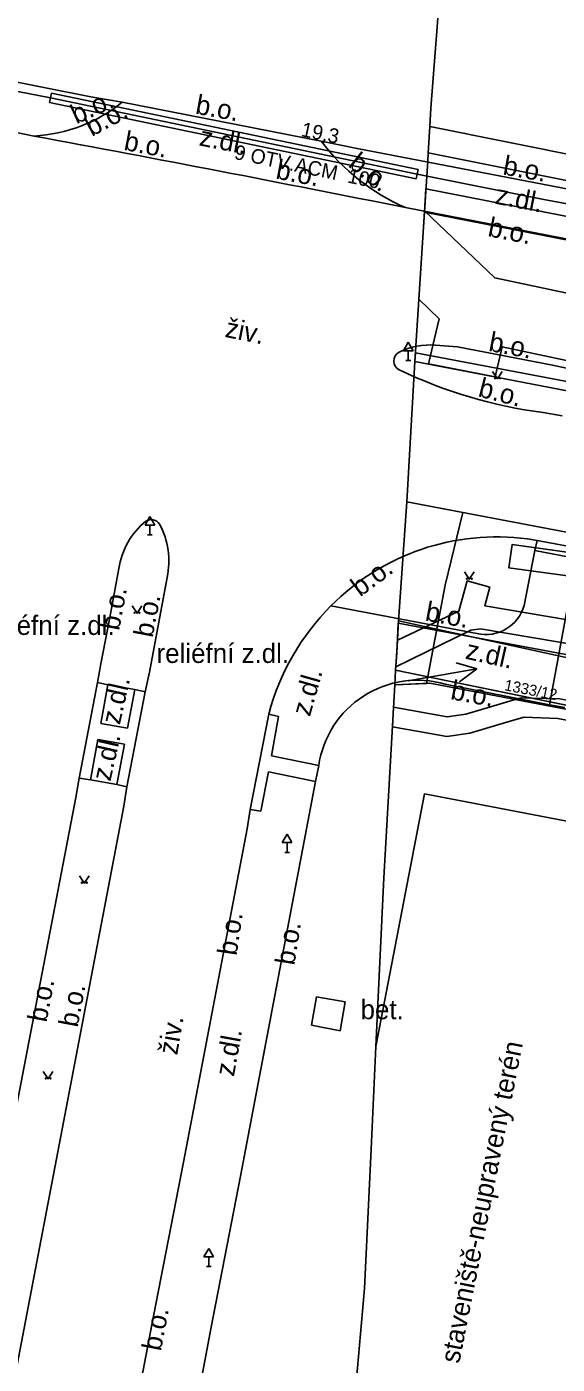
# Model space of a CAD drawing. Extents: x -601602 to -600882, y -1162594 to -1161950.
# Drawn here: x -601508 to -601480.7, y -1162340.4 to -1162271.4 of the extents above; entities that cross this region are included whole.
import ezdxf

# ---------------------------------------------------------------- set-up
doc = ezdxf.new("R2010")
doc.units = 0
for name, color, linetype in [('KN_Hranice parcel', 7, 'Continuous'), ('KN_Parcelní čísla', 7, 'Continuous'), ('KN_Pop  PČ popisy', 7, 'Continuous'), ('KN_Vnitřní kresba', 7, 'Continuous'), ('KN_Věcná břemena k části', 7, 'Continuous'), ('VRSTVA 1', 7, 'Continuous'), ('Vrstva 13', 7, 'Continuous'), ('Vrstva 14', 7, 'Continuous'), ('Vrstva 16', 7, 'Continuous'), ('VRSTVA 3', 7, 'Continuous'), ('VRSTVA 5', 7, 'Continuous'), ('Vrstva 6', 7, 'Continuous'), ('Vrstva 8', 7, 'Continuous')]:
    doc.layers.add(name, color=color, linetype=linetype)

# ---------------------------------------------------------------- blocks, each defined once
blk = doc.blocks.new('1029_83')
at = {"layer": 'KN_Pop  PČ popisy'}
for p, q in [((2.955, 0.521), (1.882, 0.84)), ((0, 0), (2.955, 0.521)), ((2.955, 0.521), (2.056, -0.146))]:
    blk.add_line(p, q, dxfattribs=at)

msp = doc.modelspace()

# ---------------------------------------------------------------- linework, layer by layer
at = {"layer": 'KN_Hranice parcel'}
for p, q in [((-601487.18, -1162275.61), (-601486.34, -1162264.83)), ((-601487.24, -1162276.56), (-601487.18, -1162275.61)), ((-601487.33, -1162277.91), (-601487.24, -1162276.56)), ((-601487.24, -1162276.56), (-601422.4, -1162289.56)), ((-601487.35, -1162278.35), (-601487.33, -1162277.91)), ((-601487.57, -1162281.75), (-601487.35, -1162278.35)), ((-601487.71, -1162283.88), (-601487.57, -1162281.75)), ((-601488.01, -1162288.67), (-601487.71, -1162283.88)), ((-601488.01, -1162288.67), (-601488.43, -1162295.92)), ((-601488.86, -1162302.06), (-601488.43, -1162295.92)), ((-601488.43, -1162295.92), (-601466.03, -1162300.16)), ((-601488.95, -1162303.71), (-601488.86, -1162302.06)), ((-601489.01, -1162304.59), (-601488.95, -1162303.71)), ((-601489.01, -1162304.59), (-601489.05, -1162305.35)), ((-601465.65, -1162309.39), (-601489.01, -1162304.59)), ((-601489.05, -1162305.35), (-601489.61, -1162315.31)), ((-601489.61, -1162315.31), (-601490.02, -1162324)), ((-601490.02, -1162324), (-601490.27, -1162329.3))]:
    msp.add_line(p, q, dxfattribs=at)
for points in [[(-601487.33, -1162277.91), (-601423.31, -1162290.7), (-601422.78, -1162290.75), (-601418.98, -1162290.19)], [(-601346.72, -1162315.75), (-601358.39, -1162313.5), (-601389.94, -1162307.57), (-601406.17, -1162304.44), (-601488.01, -1162288.67)], [(-601489.05, -1162305.35), (-601487.24, -1162305.27), (-601465.65, -1162309.39)], [(-601465.12, -1162315.27), (-601487.52, -1162310.98), (-601490.02, -1162324)], [(-601490.27, -1162329.3), (-601490.61, -1162336.49), (-601491.28, -1162344.08)]]:
    msp.add_lwpolyline(points, dxfattribs=at)
at = {"layer": 'KN_Pop  PČ popisy'}
msp.add_line((-601488.35, -1162305.15), (-601487.77, -1162305.05), dxfattribs=at)
at = {"layer": 'KN_Vnitřní kresba'}
msp.add_line((-601488.86, -1162302.06), (-601425, -1162316), dxfattribs=at)
at = {"layer": 'KN_Věcná břemena k části'}
for points in [[(-601342.91, -1162315.69), (-601475.53, -1162290.59), (-601474.19, -1162283.58), (-601472.3, -1162283.95), (-601472.05, -1162282.78), (-601487.44, -1162279.77), (-601487.52, -1162280.97), (-601475.37, -1162283.35), (-601476.71, -1162290.36), (-601487.98, -1162288.23), (-601488.01, -1162288.67), (-601406.17, -1162304.44)], [(-601470.29, -1162303.67), (-601484.41, -1162301.27), (-601484.15, -1162300.31), (-601485.31, -1162299.99), (-601485.74, -1162301.55), (-601488.91, -1162303.05), (-601489, -1162304.43), (-601485.13, -1162302.53), (-601484.63, -1162302.46), (-601471.08, -1162304.75)], [(-601429.98, -1162315.75), (-601480.53, -1162306.08), (-601481.97, -1162306.04), (-601482.51, -1162306.02), (-601482.83, -1162306.11), (-601465.65, -1162309.39), (-601426.59, -1162316.85)]]:
    msp.add_lwpolyline(points, dxfattribs=at)
for points in [[(-601319.34, -1162319.73), (-601318.72, -1162316.39), (-601326.64, -1162314.93), (-601327.32, -1162314.81), (-601389.66, -1162303.33), (-601388.27, -1162295.89), (-601391.51, -1162295.29), (-601392.9, -1162302.72), (-601436.53, -1162294.41), (-601483.89, -1162284.37), (-601487.52, -1162280.9), (-601487.57, -1162281.75), (-601487.71, -1162283.88), (-601487.81, -1162285.47), (-601486.76, -1162286.48), (-601487.31, -1162288.8), (-601483.87, -1162289.47), (-601483.5, -1162287.92), (-601437.21, -1162297.75), (-601391.91, -1162306.37), (-601327.93, -1162318.15), (-601327.24, -1162318.27)], [(-601485.54, -1162296.47), (-601488.43, -1162295.92), (-601488.86, -1162302.06), (-601488.95, -1162303.71), (-601489.01, -1162304.59), (-601489.05, -1162305.35), (-601487.41, -1162305.28), (-601487.34, -1162304.93), (-601486.44, -1162300.21)], [(-601477.35, -1162300.11), (-601476.96, -1162298.09), (-601478.14, -1162297.87), (-601478.31, -1162298.77), (-601483, -1162298.12), (-601483.17, -1162299.31)], [(-601340.46, -1162325.49), (-601340.18, -1162324.13), (-601343.62, -1162323.47), (-601343.9, -1162324.81), (-601344.69, -1162329.03), (-601344.71, -1162329.07), (-601344.93, -1162329.2), (-601345.26, -1162329.25), (-601374.56, -1162323.51), (-601392.8, -1162320.1), (-601410.16, -1162316.86), (-601424.81, -1162314.13), (-601488.87, -1162302.17), (-601488.95, -1162303.71), (-601489.01, -1162304.59), (-601465.65, -1162309.39), (-601426.59, -1162316.85), (-601404.54, -1162321.04), (-601393.45, -1162323.18), (-601344.64, -1162332.49), (-601343.79, -1162332.38), (-601342.39, -1162331.51), (-601341.29, -1162329.93)], [(-601340.7, -1162333.75), (-601340.99, -1162333.19), (-601393.45, -1162323.18), (-601404.54, -1162321.04), (-601426.59, -1162316.85), (-601465.65, -1162309.39), (-601482.83, -1162306.11), (-601485.38, -1162306.86), (-601486.35, -1162307), (-601489.12, -1162306.51), (-601489.17, -1162307.52), (-601486.36, -1162308.02), (-601485.17, -1162307.84), (-601482.92, -1162307.18), (-601482.38, -1162307.02), (-601480.64, -1162307.08), (-601432.85, -1162316.22), (-601430.16, -1162316.73), (-601428.76, -1162316.98), (-601393.64, -1162323.22), (-601393.47, -1162323.26), (-601363.36, -1162329), (-601345.3, -1162332.79)]]:
    msp.add_lwpolyline(points, close=True, dxfattribs=at)
at = {"layer": 'VRSTVA 1'}
msp.add_lwpolyline([(-601331.31, -1162306.58), (-601332.3, -1162306.37), (-601334.05, -1162306.03), (-601365.21, -1162299.85), (-601405.05, -1162291.66), (-601414.46, -1162290.57), (-601424.01, -1162291.3), (-601452.18, -1162285.72), (-601481.36, -1162280.32), (-601487.9, -1162279.02), (-601506.8, -1162275.08), (-601511.71, -1162274.13), (-601531.56, -1162268.63), (-601534.84, -1162286.8), (-601535.95, -1162290.68)], dxfattribs=at)
at = {"layer": 'Vrstva 13'}
for p, q in [((-601504.73, -1162275.03), (-601521.39, -1162271.75)), ((-601507.65, -1162277.05), (-601520.42, -1162274.54)), ((-601503.11, -1162275.31), (-601504.73, -1162275.03)), ((-601498.9, -1162276.13), (-601503.11, -1162275.31)), ((-601492.84, -1162277.32), (-601498.9, -1162276.13)), ((-601490.98, -1162277.7), (-601492.84, -1162277.32)), ((-601476.11, -1162280.56), (-601490.98, -1162277.7)), ((-601479.69, -1162282.46), (-601488.5, -1162280.74)), ((-601485.81, -1162287.93), (-601486.94, -1162287.84)), ((-601480.92, -1162288.87), (-601485.81, -1162287.93)), ((-601479.95, -1162289.08), (-601480.92, -1162288.87)), ((-601480.42, -1162291.48), (-601481.4, -1162291.31)), ((-601481.7, -1162297.91), (-601482.21, -1162297.83)), ((-601481.7, -1162297.91), (-601481.82, -1162298.42)), ((-601476.78, -1162298.83), (-601481.7, -1162297.91)), ((-601481.82, -1162298.42), (-601482.38, -1162301.26)), ((-601479.68, -1162298.84), (-601481.82, -1162298.42)), ((-601481.07, -1162306.38), (-601479.68, -1162298.84)), ((-601503.75, -1162301.88), (-601503.28, -1162299.36)), ((-601500.79, -1162299.81), (-601501.7, -1162304.7)), ((-601492.34, -1162301.28), (-601484.81, -1162302.7)), ((-601503.75, -1162301.88), (-601504.21, -1162304.27)), ((-601504.21, -1162304.27), (-601504.38, -1162305.24)), ((-601504.38, -1162305.24), (-601505.32, -1162310.16)), ((-601503.84, -1162305.35), (-601504.38, -1162305.24)), ((-601501.7, -1162304.7), (-601501.92, -1162305.71)), ((-601504.21, -1162307.34), (-601503.84, -1162305.35)), ((-601502.46, -1162305.6), (-601503.84, -1162305.35)), ((-601501.92, -1162305.71), (-601502.86, -1162310.61)), ((-601502.46, -1162305.6), (-601502.84, -1162307.59)), ((-601501.92, -1162305.71), (-601502.46, -1162305.6)), ((-601481.07, -1162306.38), (-601486.44, -1162305.32)), ((-601480.27, -1162306.52), (-601481.07, -1162306.38)), ((-601495.55, -1162306.87), (-601496.5, -1162311.78)), ((-601495.55, -1162306.87), (-601495.04, -1162306.98)), ((-601495.04, -1162306.98), (-601495.4, -1162309.02)), ((-601502.84, -1162307.59), (-601504.21, -1162307.34)), ((-601504.37, -1162308.17), (-601504.75, -1162310.25)), ((-601504.37, -1162308.17), (-601502.99, -1162308.41)), ((-601502.99, -1162308.41), (-601503.39, -1162310.5)), ((-601495.4, -1162309.02), (-601492.97, -1162309.51)), ((-601495.56, -1162309.83), (-601495.96, -1162311.87)), ((-601493.14, -1162310.34), (-601495.56, -1162309.83)), ((-601492.97, -1162309.51), (-601493.14, -1162310.34)), ((-601505.32, -1162310.16), (-601505.5, -1162311.16)), ((-601505.32, -1162310.16), (-601504.75, -1162310.25)), ((-601504.75, -1162310.25), (-601503.39, -1162310.5)), ((-601503.39, -1162310.5), (-601502.86, -1162310.61)), ((-601502.86, -1162310.61), (-601503.03, -1162311.61)), ((-601493.14, -1162310.34), (-601497, -1162330.69)), ((-601505.5, -1162311.16), (-601508.99, -1162329.34)), ((-601503.03, -1162311.61), (-601506.43, -1162329.43)), ((-601496.5, -1162311.78), (-601496.67, -1162312.78)), ((-601495.96, -1162311.87), (-601496.5, -1162311.78)), ((-601496.67, -1162312.78), (-601499.94, -1162329.96)), ((-601493.34, -1162322.9), (-601493.08, -1162321.45)), ((-601491.6, -1162321.7), (-601493.08, -1162321.45)), ((-601491.6, -1162321.7), (-601491.86, -1162323.19)), ((-601491.86, -1162323.19), (-601493.34, -1162322.9)), ((-601506.43, -1162329.43), (-601509.56, -1162345.82)), ((-601499.94, -1162329.96), (-601501.49, -1162337.91)), ((-601497, -1162330.69), (-601498.51, -1162338.48)), ((-601502.5, -1162343.17), (-601501.49, -1162337.91)), ((-601499.52, -1162343.77), (-601498.51, -1162338.48))]:
    msp.add_line(p, q, dxfattribs=at)
for centre, radius, start, end in [((-601508.095, -1162269.097), 7.966, 273.20017, 308.73948), ((-601775.062, -1163716.372), 1463.953, 78.71175, 79.475031), ((-601484.219, -1162270.843), 10.783, 216.91579, 246.60669), ((-601487.272, -1162291.193), 3.369, 84.33594, 117.34467), ((-601488.592, -1162288.655), 0.509, 116.56505, 243.43495), ((-601478.181, -1162266.842), 24.679, 244.46399, 262.50626), ((-601499.484, -1162299.906), 3.835, 128.85408, 171.80801), ((-601501.606, -1162297.349), 0.515, 34.16453, 123.52615), ((-601504.72, -1162298.965), 4.02, 347.86282, 28.28069), ((-601483.801, -1162309.755), 12.031, 82.40051, 135.21436), ((-601483.528, -1162310.057), 12.437, 135.11395, 165.15374), ((-601484.338, -1162300.726), 2.029, 256.54633, 344.755), ((-601487.879, -1162310.261), 5.146, 73.7649, 171.60794)]:
    msp.add_arc(centre, radius, start, end, dxfattribs=at)
at = {"layer": 'Vrstva 14'}
msp.add_lwpolyline([(-601502.594, -1162301.284), (-601502.344, -1162301.659), (-601502.094, -1162301.284)], dxfattribs=at)
for centre in [(-601502.469, -1162301.634), (-601502.469, -1162301.634), (-601502.219, -1162301.634), (-601502.219, -1162301.634)]:
    msp.add_circle(centre, 0.025, dxfattribs=at)
at = {"layer": 'VRSTVA 3'}
for points in [[(-601484.001, -1162289.195), (-601483.751, -1162289.57), (-601483.501, -1162289.195)], [(-601485.452, -1162299.531), (-601485.202, -1162299.906), (-601484.952, -1162299.531)], [(-601505.312, -1162315.204), (-601505.062, -1162315.579), (-601504.812, -1162315.204)], [(-601507.177, -1162325.297), (-601506.927, -1162325.672), (-601506.677, -1162325.297)]]:
    msp.add_lwpolyline(points, dxfattribs=at)
for centre in [(-601483.876, -1162289.545), (-601483.626, -1162289.545), (-601485.327, -1162299.881), (-601485.077, -1162299.881), (-601505.187, -1162315.554), (-601504.937, -1162315.554), (-601507.052, -1162325.647), (-601506.802, -1162325.647)]:
    msp.add_circle(centre, 0.025, dxfattribs=at)
at = {"layer": 'VRSTVA 5'}
for p, q in [((-601506.749, -1162274.835), (-601506.851, -1162275.325)), ((-601506.749, -1162274.835), (-601487.849, -1162278.775)), ((-601506.851, -1162275.325), (-601487.951, -1162279.265)), ((-601506.8, -1162275.08), (-601487.9, -1162279.02)), ((-601487.849, -1162278.775), (-601487.951, -1162279.265))]:
    msp.add_line(p, q, dxfattribs=at)
at = {"layer": 'Vrstva 8'}
for p, q in [((-601488.35, -1162287.687), (-601488.6, -1162288.12)), ((-601488.35, -1162287.687), (-601488.1, -1162288.12)), ((-601488.6, -1162288.12), (-601488.1, -1162288.12)), ((-601488.475, -1162288.62), (-601488.225, -1162288.62)), ((-601488.35, -1162288.62), (-601488.35, -1162288.12)), ((-601501.68, -1162296.677), (-601501.93, -1162297.11)), ((-601501.68, -1162296.677), (-601501.43, -1162297.11)), ((-601501.93, -1162297.11), (-601501.43, -1162297.11)), ((-601501.805, -1162297.61), (-601501.555, -1162297.61)), ((-601501.68, -1162297.61), (-601501.68, -1162297.11)), ((-601494.6, -1162313.057), (-601494.85, -1162313.49)), ((-601494.85, -1162313.49), (-601494.35, -1162313.49)), ((-601494.6, -1162313.057), (-601494.35, -1162313.49)), ((-601494.6, -1162313.99), (-601494.6, -1162313.49)), ((-601494.725, -1162313.99), (-601494.475, -1162313.99)), ((-601498.64, -1162334.417), (-601498.89, -1162334.85)), ((-601498.89, -1162334.85), (-601498.39, -1162334.85)), ((-601498.64, -1162334.417), (-601498.39, -1162334.85)), ((-601498.64, -1162335.35), (-601498.64, -1162334.85)), ((-601498.765, -1162335.35), (-601498.515, -1162335.35))]:
    msp.add_line(p, q, dxfattribs=at)

# ---------------------------------------------------------------- block references
at = {"layer": 'KN_Pop  PČ popisy'}
msp.add_blockref('1029_83', (-601487.77, -1162305.05), dxfattribs=at)

# ---------------------------------------------------------------- texts
at = {"layer": 'KN_Parcelní čísla'}
msp.add_text('1333/12', height=0.5695, rotation=349, dxfattribs=at).set_placement((-601483.429, -1162305.626))
at = {"layer": 'Vrstva 16'}
for s, rotation, p in [('b.o.', 349.44944, (-601499.374, -1162275.887)), ('b.o.', 24.53434, (-601505.473, -1162276.452)), ('b.o.', 28.37491, (-601504.678, -1162277.1)), ('b.o.', 349.19893, (-601503.064, -1162277.757)), ('z.dl.', 349.09339, (-601499.178, -1162277.529)), ('b.o.', 349.19893, (-601495.229, -1162279.236)), ('b.o.', 321.52262, (-601491.498, -1162278.595)), ('b.o.', 349.90323, (-601483.513, -1162279.028)), ('z.dl.', 349.11727, (-601483.925, -1162280.533)), ('b.o.', 348.84784, (-601484.29, -1162282.206)), ('živ.', 348.73612, (-601497.847, -1162287.405)), ('b.o.', 349.12541, (-601484.251, -1162288.118)), ('b.o.', 345.60156, (-601484.796, -1162290.466)), ('b.o.', 36.56019, (-601490.837, -1162300.843)), ('b.o.', 79.16848, (-601503.272, -1162302.589)), ('b.o.', 79.16848, (-601501.541, -1162302.953)), ('b.o.', 349.44337, (-601487.522, -1162302.022)), ('z.dl.', 347.37552, (-601485.454, -1162303.995)), ('z.dl.', 77.30794, (-601503.232, -1162307.446)), ('z.dl.', 74.09909, (-601493.429, -1162307.025)), ('b.o.', 349.44337, (-601486.213, -1162306.083)), ('z.dl.', 77.30794, (-601503.718, -1162310.364)), ('b.o.', 81.63795, (-601497.21, -1162319.348)), ('b.o.', 80.94772, (-601494.23, -1162319.849)), ('b.o.', 79.26717, (-601507.013, -1162322.791)), ('b.o.', 79.26717, (-601505.408, -1162323.054)), ('živ.', 80.25556, (-601500.273, -1162324.474)), ('z.dl.', 79.8237, (-601497.348, -1162325.586)), ('staveniště-neupravený terén', 78.7556, (-601485.726, -1162340.388)), ('b.o.', 79.07719, (-601501.114, -1162339.746))]:
    msp.add_text(s, height=1, rotation=rotation, dxfattribs=at).set_placement(p)
for s, p in [('reliéfní z.dl.', (-601510.333, -1162302.779)), ('reliéfní z.dl.', (-601501.336, -1162304.224)), ('bet.', (-601490.812, -1162322.597))]:
    msp.add_text(s, height=1, dxfattribs=at).set_placement(p)
at = {"layer": 'Vrstva 6'}
for s, p in [('19,3', (-601493.919, -1162277.054)), ('9 OTV.ACM  100', (-601497.367, -1162278.225))]:
    msp.add_text(s, height=0.75, rotation=348.22445, dxfattribs=at).set_placement(p)

doc.saveas('drawing.dxf')
